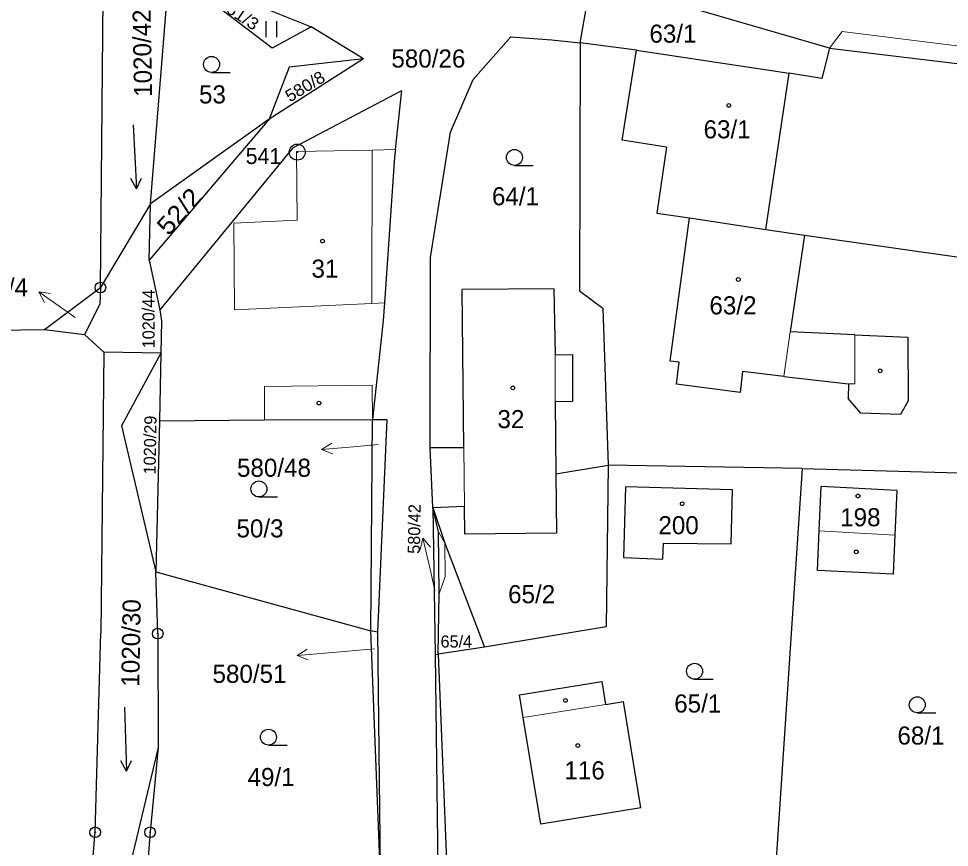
# Model space of a CAD drawing. Extents: x -601131 to -597152, y -1058536 to -1055911.
# Drawn here: x -599468.7 to -599381.2, y -1057201.3 to -1057123.5 of the extents above; entities that cross this region are included whole.
import ezdxf
from ezdxf.enums import TextEntityAlignment as Align

# ---------------------------------------------------------------- set-up
doc = ezdxf.new("R2010")
doc.units = 0
doc.header["$LTSCALE"] = 0.68
for name, color, linetype, lineweight in [('1', 7, 'Continuous', 25), ('3', 7, 'Continuous', 25), ('4', 7, 'Continuous', 13), ('5', 7, 'Continuous', 25), ('7', 7, 'Continuous', 13), ('8', 7, 'Continuous', 25)]:
    doc.layers.add(name, color=color, linetype=linetype, lineweight=lineweight)
doc.layers.add('2', color=7, linetype='Continuous')

msp = doc.modelspace()

# ---------------------------------------------------------------- linework, layer by layer
at = {"layer": '1'}
for p, q in [((-599461.04, -1057148.74), (-599460.76, -1057117.69)), ((-599456.32, -1057140.87), (-599454.57, -1057118.86)), ((-599444.88, -1057126.24), (-599454.57, -1057118.86)), ((-599454.57, -1057118.86), (-599441.23, -1057124.24)), ((-599415.94, -1057125.73), (-599414.88, -1057119.74)), ((-599392.5, -1057126.24), (-599414.88, -1057119.74)), ((-599441.23, -1057124.24), (-599444.88, -1057126.24)), ((-599436.31, -1057127.23), (-599441.23, -1057124.24)), ((-599425.99, -1057129.2), (-599422.46, -1057125.19)), ((-599422.46, -1057125.19), (-599418.6, -1057125.46)), ((-599418.6, -1057125.46), (-599415.94, -1057125.73)), ((-599415.94, -1057125.73), (-599416.01, -1057149.05)), ((-599410.65, -1057126.42), (-599415.94, -1057125.73)), ((-599412.01, -1057134.88), (-599410.65, -1057126.42)), ((-599410.65, -1057126.42), (-599396.31, -1057128.6)), ((-599392.5, -1057126.24), (-599393.23, -1057129.1)), ((-599392.5, -1057126.24), (-599357.9, -1057130.4)), ((-599436.31, -1057127.23), (-599445.17, -1057132.9)), ((-599436.31, -1057127.23), (-599443.3, -1057128.03)), ((-599443.3, -1057128.03), (-599445.17, -1057132.9)), ((-599428.12, -1057134.14), (-599425.99, -1057129.2)), ((-599398.49, -1057143.28), (-599396.31, -1057128.6)), ((-599393.23, -1057129.1), (-599396.31, -1057128.6)), ((-599442.95, -1057135.6), (-599432.71, -1057130.22)), ((-599433.31, -1057135.76), (-599432.71, -1057130.22)), ((-599445.17, -1057132.9), (-599456.45, -1057146.15)), ((-599445.17, -1057132.9), (-599456.32, -1057140.87)), ((-599430, -1057145.91), (-599428.12, -1057134.14)), ((-599407.82, -1057135.53), (-599412.01, -1057134.88)), ((-599442.95, -1057135.6), (-599455.44, -1057150.84)), ((-599433.31, -1057135.76), (-599433.39, -1057136.47)), ((-599407.82, -1057135.53), (-599408.75, -1057141.75)), ((-599433.39, -1057136.47), (-599434.34, -1057150.17)), ((-599456.32, -1057140.87), (-599461.04, -1057148.74)), ((-599456.45, -1057146.15), (-599456.32, -1057140.87)), ((-599408.75, -1057141.75), (-599405.66, -1057142.17)), ((-599407.5, -1057155.66), (-599405.66, -1057142.17)), ((-599405.66, -1057142.17), (-599398.49, -1057143.28)), ((-599398.49, -1057143.28), (-599394.87, -1057143.82)), ((-599394.87, -1057143.82), (-599396.21, -1057152.91)), ((-599394.87, -1057143.82), (-599363.04, -1057148.31)), ((-599430.06, -1057163.78), (-599430, -1057145.91)), ((-599456.45, -1057146.15), (-599455.44, -1057150.84)), ((-599466.3, -1057152.69), (-599461.04, -1057148.74)), ((-599461.04, -1057148.74), (-599461.08, -1057150.28)), ((-599418.42, -1057148.86), (-599427.04, -1057148.91)), ((-599426.87, -1057163.79), (-599427.04, -1057148.91)), ((-599418.42, -1057148.86), (-599418.31, -1057155.04)), ((-599416.01, -1057149.05), (-599413.83, -1057150.68)), ((-599461.08, -1057150.28), (-599462.54, -1057153.15)), ((-599434.34, -1057150.17), (-599434.46, -1057151.82)), ((-599455.44, -1057150.84), (-599455.29, -1057151.86)), ((-599413.83, -1057150.68), (-599413.32, -1057165.41)), ((-599455.29, -1057151.86), (-599455.35, -1057154.89)), ((-599434.46, -1057151.82), (-599435.47, -1057161.12)), ((-599481.42, -1057152.83), (-599466.3, -1057152.69)), ((-599466.3, -1057152.69), (-599462.54, -1057153.15)), ((-599390.12, -1057153.17), (-599396.21, -1057152.91)), ((-599460.72, -1057154.82), (-599462.54, -1057153.15)), ((-599390.12, -1057153.17), (-599385.14, -1057153.38)), ((-599385.14, -1057153.38), (-599385.12, -1057159.39)), ((-599460.72, -1057154.82), (-599461.01, -1057181.17)), ((-599455.35, -1057154.89), (-599460.72, -1057154.82)), ((-599455.35, -1057154.89), (-599459.04, -1057161.72)), ((-599455.35, -1057154.89), (-599455.48, -1057161.26)), ((-599418.31, -1057155.04), (-599416.66, -1057155.01)), ((-599416.66, -1057155.01), (-599416.67, -1057159.45)), ((-599406.65, -1057155.76), (-599407.5, -1057155.66)), ((-599406.89, -1057157.81), (-599406.65, -1057155.76)), ((-599400.69, -1057156.63), (-599400.92, -1057158.59)), ((-599396.82, -1057157.09), (-599400.69, -1057156.63)), ((-599396.82, -1057157.09), (-599390.74, -1057157.78)), ((-599400.92, -1057158.59), (-599406.89, -1057157.81)), ((-599390.74, -1057157.78), (-599390.76, -1057159.16)), ((-599416.67, -1057159.45), (-599418.31, -1057159.47)), ((-599418.31, -1057159.47), (-599418.23, -1057166.24)), ((-599389.57, -1057160.54), (-599390.76, -1057159.16)), ((-599385.12, -1057159.39), (-599385.84, -1057160.66)), ((-599385.84, -1057160.66), (-599389.57, -1057160.54)), ((-599455.48, -1057161.26), (-599455.84, -1057175.43)), ((-599455.48, -1057161.26), (-599445.63, -1057161.17)), ((-599445.63, -1057161.17), (-599435.47, -1057161.12)), ((-599435.62, -1057180.98), (-599435.47, -1057161.12)), ((-599435.47, -1057161.12), (-599434.13, -1057161.14)), ((-599434.13, -1057161.14), (-599434.99, -1057181.12)), ((-599459.04, -1057161.72), (-599455.84, -1057175.43)), ((-599426.87, -1057163.79), (-599430.06, -1057163.78)), ((-599429.78, -1057169.39), (-599430.06, -1057163.78)), ((-599418.23, -1057166.24), (-599413.32, -1057165.41)), ((-599413.32, -1057165.41), (-599413.52, -1057180.61)), ((-599395.07, -1057165.74), (-599413.32, -1057165.41)), ((-599395.07, -1057165.74), (-599397.77, -1057205.96)), ((-599395.07, -1057165.74), (-599365.52, -1057166.56)), ((-599418.23, -1057166.24), (-599418.17, -1057171.82)), ((-599393.48, -1057171.6), (-599393.31, -1057167.42)), ((-599386.18, -1057167.81), (-599393.31, -1057167.42)), ((-599386.18, -1057167.81), (-599386.37, -1057171.99)), ((-599429.78, -1057169.39), (-599426.81, -1057169.27)), ((-599429.78, -1057169.39), (-599429.59, -1057183.22)), ((-599429.27, -1057171.69), (-599429.78, -1057169.39)), ((-599429.78, -1057169.39), (-599428.66, -1057172.76)), ((-599426.78, -1057171.92), (-599426.81, -1057169.27)), ((-599429.2, -1057177.51), (-599429.27, -1057171.69)), ((-599418.17, -1057171.82), (-599426.78, -1057171.92)), ((-599393.64, -1057175.32), (-599393.48, -1057171.6)), ((-599386.37, -1057171.99), (-599386.54, -1057175.65)), ((-599428.66, -1057172.76), (-599424.95, -1057182.53)), ((-599455.65, -1057181.25), (-599455.84, -1057175.43)), ((-599455.84, -1057175.43), (-599435.62, -1057180.98)), ((-599386.54, -1057175.65), (-599393.64, -1057175.32)), ((-599429.29, -1057183.18), (-599429.2, -1057177.51)), ((-599413.52, -1057180.61), (-599424.95, -1057182.53)), ((-599461.53, -1057199.92), (-599461.01, -1057181.17)), ((-599455.65, -1057181.25), (-599455.61, -1057191.95)), ((-599434.99, -1057181.12), (-599435.62, -1057180.98)), ((-599434.72, -1057204.36), (-599435.62, -1057180.98)), ((-599434.99, -1057181.12), (-599434.72, -1057204.36)), ((-599424.95, -1057182.53), (-599429.29, -1057183.18)), ((-599429.59, -1057183.22), (-599429.29, -1057183.18)), ((-599429.59, -1057183.22), (-599429.07, -1057220.62)), ((-599429.29, -1057183.18), (-599428.41, -1057205.25)), ((-599421.64, -1057187.01), (-599413.91, -1057185.75)), ((-599413.91, -1057185.75), (-599413.56, -1057187.91)), ((-599421.29, -1057189.14), (-599421.64, -1057187.01)), ((-599413.56, -1057187.91), (-599411.88, -1057187.63)), ((-599410.25, -1057197.61), (-599411.88, -1057187.63)), ((-599419.66, -1057199.15), (-599421.29, -1057189.14)), ((-599455.61, -1057191.95), (-599461.31, -1057215.89)), ((-599455.61, -1057191.95), (-599456.37, -1057199.92)), ((-599410.25, -1057197.61), (-599419.66, -1057199.15)), ((-599461.78, -1057202.87), (-599461.53, -1057199.92)), ((-599456.37, -1057199.92), (-599456.62, -1057203))]:
    msp.add_line(p, q, dxfattribs=at)
msp.add_lwpolyline([(-599401.62, -1057167.74), (-599411.68, -1057167.45), (-599411.88, -1057174.09), (-599408.18, -1057174.24), (-599408.12, -1057172.76), (-599401.77, -1057172.8)], close=True, dxfattribs=at)
at = {"layer": '3'}
for p, q in [((-599445.461, -1057125.21), (-599445.461, -1057123.71)), ((-599444.46, -1057125.21), (-599444.46, -1057123.71)), ((-599450.593, -1057128.52), (-599448.843, -1057128.52)), ((-599422.123, -1057137.26), (-599420.373, -1057137.26)), ((-599457.641, -1057139.443), (-599458.193, -1057138.494)), ((-599446.143, -1057168.41), (-599444.393, -1057168.41)), ((-599405.193, -1057185.54), (-599403.443, -1057185.54)), ((-599384.263, -1057188.69), (-599382.513, -1057188.69)), ((-599445.243, -1057191.73), (-599443.493, -1057191.73)), ((-599458.573, -1057194.166), (-599459.108, -1057193.207))]:
    msp.add_line(p, q, dxfattribs=at)
for points in [[(-599457.955, -1057133.452), (-599457.641, -1057139.443), (-599457.191, -1057138.441)], [(-599458.783, -1057188.169), (-599458.573, -1057194.166), (-599458.106, -1057193.172)]]:
    msp.add_lwpolyline(points, dxfattribs=at)
for centre in [(-599450.5929, -1057127.7698), (-599422.1229, -1057136.5098), (-599446.1429, -1057167.6598), (-599405.1929, -1057184.7898), (-599384.2629, -1057187.9398), (-599445.2429, -1057190.9798)]:
    msp.add_circle(centre, 0.75, dxfattribs=at)
at = {"layer": '4'}
for p, q in [((-599392.5, -1057126.24), (-599391.34, -1057124.68)), ((-599391.34, -1057124.68), (-599358.33, -1057128.81)), ((-599442.6, -1057135.96), (-599435.5, -1057135.81)), ((-599442.54, -1057142.41), (-599442.6, -1057135.96)), ((-599435.5, -1057135.81), (-599433.31, -1057135.76)), ((-599448.51, -1057142.68), (-599442.54, -1057142.41)), ((-599396.82, -1057157.09), (-599396.21, -1057152.91)), ((-599390.12, -1057153.17), (-599390.13, -1057157.78)), ((-599418.31, -1057155.04), (-599418.31, -1057159.47)), ((-599445.63, -1057158.02), (-599435.49, -1057157.91)), ((-599445.63, -1057158.02), (-599445.63, -1057161.17)), ((-599435.49, -1057157.91), (-599435.47, -1057161.12)), ((-599390.13, -1057157.78), (-599390.74, -1057157.78)), ((-599426.81, -1057169.27), (-599426.87, -1057163.79)), ((-599429.27, -1057171.69), (-599428.66, -1057172.76)), ((-599393.48, -1057171.6), (-599386.37, -1057171.99)), ((-599428.66, -1057172.76), (-599428.63, -1057175.89)), ((-599428.63, -1057175.89), (-599429.2, -1057177.51)), ((-599413.56, -1057187.91), (-599421.29, -1057189.14))]:
    msp.add_line(p, q, dxfattribs=at)
for points in [[(-599435.5, -1057135.81), (-599435.52, -1057150.22), (-599434.34, -1057150.17)], [(-599448.51, -1057142.68), (-599448.42, -1057150.82), (-599435.52, -1057150.22)]]:
    msp.add_lwpolyline(points, dxfattribs=at)
at = {"layer": '5'}
for centre in [(-599401.9668, -1057131.6192), (-599440.1668, -1057144.3692), (-599401.0868, -1057147.9792), (-599387.7468, -1057156.5592), (-599422.2768, -1057158.1592), (-599440.4968, -1057159.5892), (-599389.8368, -1057168.3192), (-599406.3568, -1057169.0492), (-599389.9968, -1057173.5692), (-599417.3368, -1057187.5292), (-599416.1768, -1057191.7692)]:
    msp.add_circle(centre, 0.175, dxfattribs=at)
at = {"layer": '7'}
for p, q in [((-599466.838, -1057149.139), (-599466.305, -1057150.123)), ((-599440.25, -1057163.952), (-599439.208, -1057164.363)), ((-599430.725, -1057172.276), (-599430.988, -1057173.364)), ((-599442.55, -1057183.312), (-599441.508, -1057183.723))]:
    msp.add_line(p, q, dxfattribs=at)
for points in [[(-599463.41, -1057151.54), (-599464.38, -1057150.86), (-599466.838, -1057149.139), (-599465.731, -1057149.303)], [(-599434.94, -1057163.48), (-599437.26, -1057163.69), (-599440.25, -1057163.952), (-599439.296, -1057163.365)], [(-599429.6, -1057177.19), (-599430.05, -1057175.2), (-599430.725, -1057172.276), (-599430.012, -1057173.139)], [(-599435.29, -1057182.69), (-599439.56, -1057183.05), (-599442.55, -1057183.312), (-599441.596, -1057182.725)]]:
    msp.add_lwpolyline(points, dxfattribs=at)
at = {"layer": '8'}
for centre, radius in [((-599442.54, -1057136.0098), 0.75), ((-599442.54, -1057136.0098), 0.03), ((-599461.04, -1057148.7399), 0.5), ((-599461.04, -1057148.7399), 0.0303), ((-599455.65, -1057181.2499), 0.5), ((-599455.65, -1057181.2499), 0.0303), ((-599461.53, -1057199.9199), 0.5), ((-599461.53, -1057199.9199), 0.0303), ((-599456.37, -1057199.9199), 0.5), ((-599456.37, -1057199.9199), 0.0303)]:
    msp.add_circle(centre, radius, dxfattribs=at)

# ---------------------------------------------------------------- texts
at = {"layer": '2'}
for s, height, rotation, width, p in [('61/3', 1.14, 326, 1.1, (-599449.339, -1057122.796)), ('580/8', 1.14, 31, 1.05, (-599443.233, -1057131.354)), ('52/2', 1.7, 48, 1.1, (-599454.634, -1057143.954))]:
    msp.add_text(s, height=height, rotation=rotation, dxfattribs=dict(at, width=width)).set_placement(p)
for s, height, rotation, p in [('1020/42', 1.7, 91, (-599456.175, -1057130.802)), ('1020/44', 1.14, 90, (-599455.945, -1057154.44)), ('1020/29', 1.14, 89, (-599455.855, -1057166.294)), ('1020/30', 1.7, 89, (-599457.385, -1057186.247))]:
    msp.add_text(s, height=height, rotation=rotation, dxfattribs=at).set_placement(p)
for s, height, p in [('63/1', 1.7, (-599409.44, -1057125.725)), ('580/26', 1.7, (-599433.69, -1057128.064)), ('53', 1.7, (-599451.77, -1057131.435)), ('63/1', 1.7, (-599404.35, -1057134.715)), ('64/1', 1.7, (-599424.24, -1057141.005)), ('31', 1.7, (-599441.2, -1057147.804)), ('63/2', 1.7, (-599403.8, -1057151.255)), ('32', 1.7, (-599423.72, -1057161.945)), ('198', 1.7, (-599391.51, -1057171.165)), ('50/3', 1.7, (-599448.25, -1057172.215)), ('65/2', 1.7, (-599422.72, -1057178.395)), ('65/4', 1.14, (-599429.07, -1057182.565)), ('65/1', 1.7, (-599407.11, -1057188.665)), ('68/1', 1.7, (-599386.13, -1057191.675)), ('49/1', 1.7, (-599447.21, -1057195.574)), ('116', 1.7, (-599417.43, -1057194.945))]:
    msp.add_text(s, height=height, dxfattribs=at).set_placement(p)
for s, p in [('54/4', (-599467.839, -1057149.564)), ('580/48', (-599441.249, -1057166.515)), ('580/51', (-599443.549, -1057185.875))]:
    msp.add_text(s, height=1.7, dxfattribs=at).set_placement(p, align=Align.RIGHT)
msp.add_text('580/42', height=1.14, rotation=89, dxfattribs=at).set_placement((-599430.9347, -1057169.0949), align=Align.RIGHT)
msp.add_text('200', height=1.7, dxfattribs=at).set_placement((-599406.699, -1057171.915), align=Align.CENTER)
at = {"layer": '8'}
msp.add_text('541', height=1.5, dxfattribs=at).set_placement((-599444.039, -1057137.127), align=Align.RIGHT)

doc.saveas('drawing.dxf')
